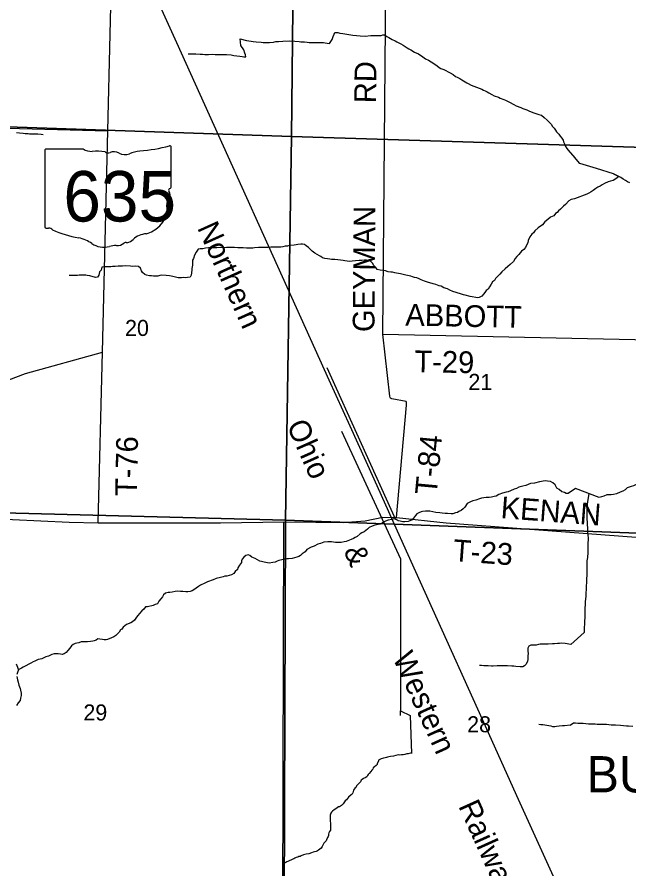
# Model space of a CAD drawing. Extents: x 1588073 to 2013523, y 1090242 to 1357120.
# Drawn here: x 1754621 to 1763053, y 1191885 to 1203633 of the extents above; entities that cross this region are included whole.
import ezdxf

# ---------------------------------------------------------------- set-up
doc = ezdxf.new("R2010")
doc.units = 0
for name, color, linetype in [('GM_X_Corporation_Text', 7, 'Continuous'), ('GM_X_Minor_River', 7, 'Continuous'), ('GM_X_Rail_Line', 7, 'Continuous'), ('GM_X_Rail_Line_Text', 7, 'Continuous'), ('GM_X_Section', 7, 'Continuous'), ('GM_X_Section_Text', 7, 'Continuous'), ('GM_X_State_Location', 7, 'Continuous'), ('GM_X_State_Route', 7, 'Continuous'), ('GM_X_State_Shield', 7, 'Continuous'), ('GM_X_Township_Road', 7, 'Continuous'), ('GM_X_Township_Road_Text', 7, 'Continuous')]:
    doc.layers.add(name, color=color, linetype=linetype)

msp = doc.modelspace()

# ---------------------------------------------------------------- linework, layer by layer
at = {"layer": 'GM_X_Minor_River'}
for p, q in [((1758889, 1198801), (1759836, 1196705)), ((1759092, 1197922), (1759904, 1196164)), ((1759904, 1196164), (1759904, 1196164)), ((1759904, 1196164), (1759905, 1194064)), ((1759905, 1194001), (1759905, 1194068)), ((1759905, 1194068), (1760040, 1194001)), ((1760040, 1194001), (1760040, 1194001)), ((1760040, 1194001), (1760055, 1193477))]:
    msp.add_line(p, q, dxfattribs=at)
for points in [[(1756979, 1203124), (1757025, 1203127), (1757085, 1203123), (1757145, 1203121), (1757177, 1203121), (1757207, 1203117), (1757233, 1203115), (1757261, 1203115), (1757321, 1203119), (1757351, 1203117), (1757399, 1203118), (1757479, 1203114), (1757505, 1203114), (1757573, 1203112), (1757606, 1203104), (1757690, 1203092), (1757722, 1203088), (1757748, 1203086), (1757774, 1203083), (1757768, 1203113), (1757758, 1203135), (1757746, 1203179), (1757707, 1203241), (1757701, 1203285), (1757695, 1203331), (1757781, 1203309), (1757847, 1203301), (1757873, 1203295), (1757916, 1203289), (1757984, 1203284), (1758014, 1203282), (1758102, 1203280), (1758154, 1203286), (1758188, 1203294), (1758222, 1203294), (1758282, 1203298), (1758374, 1203303), (1758450, 1203299), (1758508, 1203297), (1758532, 1203293), (1758583, 1203289), (1758617, 1203285), (1758647, 1203283), (1758679, 1203282), (1758719, 1203280), (1758759, 1203280), (1758783, 1203282), (1758805, 1203282), (1758843, 1203280), (1758869, 1203276), (1758895, 1203274), (1758925, 1203270), (1758947, 1203294), (1758963, 1203324), (1758979, 1203365), (1758989, 1203395), (1758999, 1203421), (1759043, 1203419), (1759071, 1203411), (1759111, 1203405), (1759193, 1203393), (1759247, 1203381), (1759347, 1203372), (1759420, 1203368), (1759494, 1203376), (1759522, 1203378), (1759584, 1203376), (1759638, 1203380), (1759660, 1203385), (1759684, 1203385), (1759716, 1203363), (1759746, 1203349), (1759792, 1203321), (1759830, 1203303), (1759854, 1203293), (1759911, 1203261), (1759943, 1203245), (1759971, 1203227), (1759997, 1203209), (1760021, 1203193), (1760047, 1203179), (1760099, 1203147), (1760153, 1203123), (1760213, 1203085), (1760250, 1203055), (1760292, 1203039), (1760364, 1202994), (1760412, 1202962), (1760440, 1202936), (1760462, 1202924), (1760502, 1202908), (1760589, 1202864), (1760631, 1202842), (1760661, 1202814), (1760685, 1202802), (1760723, 1202786), (1760749, 1202768), (1760773, 1202752), (1760817, 1202726), (1760839, 1202714), (1760880, 1202694)], [(1760880, 1202694), (1760952, 1202664), (1760990, 1202650), (1761026, 1202636), (1761050, 1202625), (1761072, 1202615), (1761098, 1202601), (1761124, 1202589), (1761162, 1202565), (1761198, 1202547), (1761254, 1202529), (1761279, 1202513), (1761329, 1202497), (1761351, 1202485), (1761405, 1202461), (1761467, 1202427), (1761501, 1202407), (1761565, 1202385), (1761591, 1202371), (1761644, 1202354), (1761674, 1202338), (1761730, 1202318), (1761756, 1202308), (1761812, 1202290), (1761846, 1202278), (1761886, 1202246), (1761924, 1202210), (1761948, 1202188), (1761981, 1202154), (1762001, 1202124), (1762021, 1202100), (1762043, 1202072), (1762057, 1202048), (1762089, 1202018), (1762107, 1201992), (1762129, 1201964), (1762145, 1201934), (1762153, 1201910), (1762164, 1201884), (1762176, 1201856), (1762198, 1201818), (1762214, 1201796), (1762308, 1201693)], [(1754614, 1202041), (1754654, 1202037), (1754706, 1202033), (1754732, 1202029), (1754772, 1202025), (1754794, 1202023), (1754856, 1202024), (1754880, 1202022), (1754906, 1202020), (1754951, 1202016), (1754979, 1202014)], [(1762841, 1201471), (1762606, 1201542), (1762376, 1201615), (1762302, 1201700)], [(1762915, 1201434), (1762873, 1201400), (1762834, 1201380), (1762800, 1201371), (1762768, 1201359), (1762716, 1201339), (1762683, 1201318), (1762655, 1201302), (1762623, 1201286), (1762595, 1201268), (1762558, 1201241), (1762532, 1201223), (1762500, 1201205), (1762472, 1201189), (1762303, 1201128)], [(1763066, 1201346), (1763035, 1201358), (1763007, 1201377), (1762975, 1201397), (1762941, 1201421), (1762913, 1201436), (1762875, 1201454), (1762841, 1201471), (1762915, 1201434)], [(1762303, 1201128), (1762256, 1201118), (1762224, 1201096), (1762178, 1201046), (1762150, 1201024), (1762112, 1200985), (1762084, 1200961), (1762062, 1200939), (1762040, 1200925), (1762018, 1200893), (1761974, 1200871), (1761936, 1200842), (1761896, 1200808), (1761860, 1200766), (1761800, 1200728), (1761754, 1200684), (1761738, 1200657), (1761714, 1200639), (1761688, 1200603), (1761666, 1200551), (1761658, 1200517), (1761641, 1200489), (1761627, 1200455), (1761605, 1200426), (1761571, 1200406), (1761537, 1200356), (1761509, 1200330), (1761483, 1200304), (1761461, 1200264), (1761415, 1200221), (1761385, 1200195), (1761347, 1200161), (1761301, 1200117), (1761275, 1200087), (1761249, 1200066), (1761213, 1200026), (1761199, 1200000), (1761175, 1199982), (1761153, 1199950), (1761131, 1199914), (1761111, 1199880), (1761087, 1199860), (1761065, 1199833), (1761050, 1199809), (1761026, 1199785), (1760990, 1199765), (1760964, 1199763), (1760941, 1199765), (1760893, 1199775), (1760867, 1199781), (1760797, 1199799), (1760771, 1199804), (1760731, 1199818), (1760627, 1199846), (1760585, 1199866), (1760555, 1199884), (1760504, 1199900), (1760464, 1199920), (1760440, 1199926), (1760390, 1199944), (1760356, 1199956), (1760278, 1199978), (1760236, 1199991), (1760214, 1199999), (1760188, 1200011), (1760162, 1200021), (1760128, 1200035), (1760099, 1200041), (1760069, 1200051), (1760047, 1200061), (1760001, 1200069), (1759979, 1200073), (1759907, 1200091), (1759877, 1200097), (1759851, 1200101), (1759829, 1200105), (1759795, 1200113), (1759773, 1200116), (1759737, 1200120), (1759699, 1200134), (1759671, 1200138), (1759625, 1200142), (1759584, 1200150), (1759564, 1200180), (1759536, 1200206), (1759518, 1200238), (1759498, 1200260), (1759472, 1200274), (1759438, 1200280), (1759408, 1200278), (1759374, 1200276), (1759334, 1200276), (1759286, 1200270), (1759240, 1200265), (1759206, 1200263), (1759168, 1200267), (1759139, 1200273), (1759115, 1200277), (1759043, 1200283), (1758999, 1200289), (1758975, 1200291)], [(1758975, 1200291), (1758953, 1200291), (1758929, 1200293), (1758897, 1200297), (1758861, 1200304), (1758831, 1200314), (1758809, 1200330), (1758787, 1200340), (1758723, 1200378), (1758688, 1200406), (1758638, 1200456), (1758606, 1200480), (1758582, 1200496), (1758556, 1200502), (1758530, 1200502), (1758490, 1200496), (1758466, 1200490), (1758440, 1200488), (1758372, 1200482), (1758346, 1200475), (1758316, 1200471), (1758284, 1200465), (1758254, 1200461), (1758214, 1200459), (1758155, 1200461), (1758119, 1200461), (1758083, 1200457), (1758053, 1200455), (1757947, 1200454), (1757893, 1200448), (1757871, 1200446), (1757839, 1200444), (1757785, 1200446), (1757737, 1200448), (1757691, 1200452), (1757665, 1200451), (1757619, 1200455), (1757559, 1200453), (1757505, 1200453), (1757466, 1200451), (1757418, 1200453), (1757372, 1200451), (1757296, 1200448), (1757258, 1200448), (1757220, 1200444), (1757182, 1200438), (1757142, 1200436), (1757116, 1200430), (1757090, 1200390), (1757068, 1200348), (1757054, 1200305), (1757040, 1200281), (1757038, 1200247), (1757037, 1200211), (1757031, 1200167), (1757029, 1200145), (1757025, 1200105), (1757019, 1200075), (1757005, 1200047), (1756969, 1200040), (1756941, 1200038), (1756915, 1200040), (1756887, 1200038), (1756843, 1200038), (1756803, 1200046), (1756769, 1200056), (1756722, 1200062), (1756674, 1200068), (1756612, 1200074), (1756588, 1200067), (1756560, 1200061), (1756534, 1200059), (1756500, 1200059), (1756472, 1200063), (1756444, 1200065), (1756406, 1200075), (1756380, 1200081), (1756350, 1200109), (1756338, 1200133), (1756324, 1200171), (1756295, 1200193), (1756259, 1200197), (1756217, 1200195), (1756185, 1200197), (1756113, 1200200), (1756073, 1200198), (1756047, 1200198), (1756013, 1200196), (1755971, 1200194), (1755935, 1200192), (1755911, 1200190), (1755879, 1200188), (1755853, 1200188), (1755815, 1200186), (1755789, 1200185), (1755779, 1200141), (1755759, 1200119), (1755747, 1200071), (1755729, 1200047), (1755703, 1200039), (1755625, 1200065)], [(1755625, 1200065), (1755589, 1200069), (1755567, 1200071), (1755541, 1200075), (1755515, 1200072), (1755477, 1200072), (1755453, 1200070), (1755412, 1200068), (1755362, 1200068), (1755340, 1200070)], [(1762315, 1197133), (1762217, 1197061), (1762187, 1197063), (1762165, 1197075), (1762130, 1197087), (1762090, 1197117), (1762060, 1197135), (1762038, 1197181), (1762004, 1197211), (1761970, 1197229), (1761932, 1197233), (1761898, 1197235), (1761820, 1197223), (1761752, 1197206), (1761698, 1197202), (1761630, 1197172), (1761589, 1197162), (1761535, 1197148), (1761505, 1197131), (1761471, 1197123), (1761421, 1197099), (1761389, 1197087), (1761361, 1197081), (1761309, 1197065), (1761261, 1197047), (1761225, 1197028), (1761195, 1197022), (1761159, 1197012), (1761129, 1197008), (1761085, 1197008), (1761021, 1196998), (1760995, 1196988), (1760945, 1196969), (1760903, 1196961), (1760871, 1196949), (1760825, 1196927), (1760791, 1196875), (1760767, 1196849), (1760743, 1196829), (1760711, 1196814), (1760689, 1196800), (1760663, 1196796), (1760627, 1196784), (1760603, 1196782), (1760553, 1196786), (1760519, 1196788), (1760479, 1196792), (1760447, 1196794), (1760391, 1196801), (1760311, 1196817), (1760281, 1196819), (1760250, 1196817), (1760210, 1196815), (1760188, 1196811), (1760158, 1196795), (1760130, 1196781), (1760110, 1196759), (1760084, 1196724), (1760064, 1196700), (1760032, 1196686), (1760010, 1196676), (1759964, 1196670), (1759938, 1196670), (1759902, 1196680), (1759874, 1196688), (1759846, 1196706), (1759812, 1196712), (1759784, 1196706), (1759736, 1196695), (1759700, 1196679), (1759678, 1196671), (1759656, 1196657), (1759626, 1196641), (1759598, 1196637), (1759550, 1196627), (1759516, 1196613), (1759474, 1196592), (1759452, 1196572), (1759428, 1196552), (1759406, 1196534), (1759374, 1196520), (1759350, 1196506), (1759306, 1196468), (1759280, 1196455), (1759258, 1196443), (1759226, 1196429), (1759204, 1196421), (1759156, 1196401), (1759128, 1196395), (1759086, 1196387), (1759062, 1196385), (1759010, 1196387), (1758980, 1196392), (1758956, 1196394), (1758926, 1196396), (1758904, 1196396), (1758848, 1196390), (1758802, 1196374), (1758768, 1196364), (1758714, 1196336), (1758673, 1196323)], [(1763471, 1197221), (1763433, 1197221), (1763399, 1197223), (1763296, 1197224), (1763256, 1197223), (1763208, 1197207), (1763172, 1197187), (1763142, 1197180), (1763115, 1197168), (1763083, 1197160), (1763057, 1197150), (1763029, 1197139), (1763003, 1197113), (1762968, 1197097), (1762930, 1197080), (1762880, 1197058), (1762842, 1197048), (1762809, 1197045), (1762777, 1197045), (1762749, 1197043), (1762707, 1197028), (1762677, 1197018), (1762643, 1197008), (1762315, 1197133)], [(1762502, 1197062), (1762482, 1196946), (1762477, 1196914), (1762475, 1196864), (1762473, 1196835), (1762472, 1196759), (1762473, 1196713), (1762477, 1196665), (1762479, 1196631), (1762480, 1196589), (1762482, 1196553), (1762484, 1196527), (1762487, 1196489), (1762489, 1196452), (1762491, 1196422), (1762488, 1196384), (1762487, 1196286), (1762485, 1196248), (1762480, 1196182), (1762472, 1196136), (1762471, 1196018), (1762472, 1195975), (1762472, 1195931), (1762469, 1195889), (1762467, 1195833), (1762464, 1195793), (1762464, 1195745), (1762459, 1195687), (1762457, 1195641), (1762454, 1195609), (1762450, 1195567), (1762450, 1195525), (1762447, 1195491), (1762445, 1195442), (1762444, 1195348), (1762441, 1195306), (1762439, 1195258), (1762437, 1195220), (1762436, 1195182), (1762438, 1195148), (1762252, 1194981)], [(1758673, 1196323), (1758615, 1196289), (1758590, 1196259), (1758548, 1196231), (1758528, 1196209), (1758502, 1196195), (1758476, 1196184), (1758444, 1196174), (1758414, 1196166), (1758361, 1196162), (1758339, 1196162), (1758305, 1196158), (1758271, 1196150), (1758229, 1196138), (1758207, 1196130), (1758179, 1196117), (1758145, 1196111), (1758097, 1196103), (1758047, 1196109), (1758025, 1196115), (1757991, 1196127), (1757967, 1196131), (1757933, 1196147), (1757903, 1196165), (1757855, 1196185), (1757831, 1196209), (1757808, 1196219), (1757772, 1196207), (1757748, 1196186), (1757723, 1196158), (1757715, 1196134), (1757713, 1196110), (1757685, 1196074), (1757665, 1196036), (1757661, 1196014), (1757627, 1195986), (1757609, 1195961), (1757575, 1195943), (1757545, 1195933), (1757511, 1195925), (1757483, 1195921), (1757461, 1195913), (1757425, 1195903), (1757365, 1195889), (1757323, 1195872), (1757245, 1195844), (1757207, 1195828), (1757151, 1195798), (1757121, 1195780), (1757087, 1195755), (1757055, 1195733), (1757033, 1195721), (1757005, 1195713), (1756975, 1195705), (1756945, 1195707), (1756907, 1195709), (1756872, 1195711), (1756826, 1195715), (1756802, 1195709), (1756758, 1195700), (1756728, 1195698), (1756702, 1195698), (1756666, 1195690), (1756638, 1195666), (1756626, 1195640), (1756602, 1195610), (1756576, 1195576), (1756556, 1195543), (1756524, 1195531), (1756496, 1195519), (1756418, 1195501), (1756390, 1195499), (1756366, 1195467), (1756342, 1195445), (1756308, 1195410), (1756283, 1195382), (1756269, 1195358), (1756239, 1195318), (1756213, 1195294), (1756191, 1195280), (1756127, 1195257), (1756085, 1195219), (1756067, 1195193), (1756045, 1195181), (1756029, 1195149), (1756007, 1195127), (1755981, 1195105), (1755955, 1195088), (1755923, 1195072), (1755869, 1195050), (1755847, 1195046), (1755823, 1195046), (1755799, 1195048), (1755763, 1195056), (1755735, 1195058), (1755709, 1195042), (1755685, 1195032), (1755663, 1195026), (1755635, 1195023), (1755590, 1195019), (1755534, 1195019)], [(1755534, 1195019), (1755504, 1195015), (1755472, 1195005), (1755446, 1195001), (1755420, 1194995), (1755396, 1194981), (1755370, 1194963), (1755350, 1194928), (1755322, 1194900), (1755298, 1194870), (1755270, 1194852), (1755242, 1194842), (1755220, 1194848), (1755188, 1194850), (1755130, 1194852), (1755102, 1194843), (1755074, 1194829), (1755052, 1194821), (1755018, 1194809), (1754988, 1194795), (1754962, 1194785), (1754940, 1194779), (1754912, 1194773), (1754866, 1194751), (1754844, 1194742), (1754812, 1194722), (1754784, 1194708), (1754744, 1194686), (1754706, 1194666), (1754684, 1194652), (1754656, 1194642), (1754632, 1194634)], [(1762252, 1194981), (1762176, 1194994), (1762122, 1194998), (1762098, 1194995), (1762070, 1194995), (1762028, 1194989), (1761998, 1194989), (1761942, 1194983), (1761828, 1194983), (1761806, 1194979), (1761776, 1194972), (1761722, 1194972), (1761700, 1194972), (1761672, 1194956), (1761660, 1194930), (1761662, 1194890), (1761664, 1194858), (1761662, 1194824), (1761660, 1194802), (1761658, 1194776), (1761654, 1194746), (1761634, 1194705), (1761612, 1194685), (1761590, 1194673), (1761554, 1194671), (1761494, 1194677), (1761468, 1194681), (1761440, 1194681), (1761378, 1194687), (1761348, 1194687), (1761312, 1194688), (1761282, 1194688), (1761236, 1194684), (1761182, 1194682), (1761158, 1194682), (1761114, 1194684), (1761079, 1194688), (1761055, 1194688), (1761021, 1194690), (1760995, 1194692)], [(1754641, 1194637), (1754630, 1194662), (1754624, 1194688), (1754614, 1194710)], [(1754641, 1194633), (1754625, 1194593), (1754620, 1194567)], [(1754618, 1194541), (1754626, 1194491), (1754638, 1194459), (1754644, 1194421), (1754664, 1194375), (1754670, 1194351), (1754678, 1194311), (1754676, 1194276), (1754667, 1194242), (1754663, 1194206), (1754637, 1194178), (1754615, 1194140)], [(1762243, 1193867), (1762289, 1193902), (1762317, 1193900), (1762349, 1193896), (1762381, 1193896), (1762424, 1193897), (1762494, 1193888), (1762522, 1193886), (1762586, 1193885), (1762614, 1193883), (1762676, 1193881), (1762746, 1193880), (1762810, 1193875), (1762868, 1193873), (1762936, 1193868), (1763019, 1193859), (1763045, 1193857), (1763105, 1193854)], [(1762243, 1193867), (1762167, 1193861), (1762137, 1193859), (1762091, 1193854), (1762057, 1193848), (1762033, 1193844), (1762003, 1193846), (1761981, 1193854), (1761947, 1193860), (1761893, 1193868), (1761867, 1193872), (1761839, 1193874), (1761813, 1193878)], [(1760056, 1193480), (1760042, 1193484), (1760010, 1193475), (1759994, 1193471), (1759978, 1193466), (1759964, 1193464), (1759943, 1193461), (1759921, 1193457), (1759889, 1193454), (1759871, 1193457), (1759841, 1193449), (1759809, 1193442), (1759767, 1193435), (1759742, 1193432), (1759728, 1193426), (1759714, 1193422), (1759696, 1193417), (1759672, 1193413), (1759640, 1193402), (1759619, 1193395), (1759603, 1193387), (1759601, 1193371), (1759584, 1193340), (1759582, 1193326), (1759571, 1193310), (1759545, 1193294), (1759530, 1193279), (1759522, 1193261), (1759512, 1193247), (1759497, 1193229), (1759474, 1193202), (1759458, 1193188), (1759448, 1193173), (1759439, 1193155), (1759419, 1193141), (1759395, 1193132), (1759376, 1193120), (1759362, 1193109), (1759352, 1193089), (1759339, 1193075), (1759321, 1193054), (1759300, 1193030), (1759296, 1193012), (1759279, 1193006), (1759267, 1192985), (1759259, 1192971), (1759246, 1192937), (1759239, 1192917), (1759225, 1192908), (1759188, 1192876), (1759159, 1192839), (1759141, 1192823), (1759132, 1192810), (1759126, 1192796), (1759114, 1192782), (1759091, 1192761), (1759063, 1192743), (1759049, 1192740), (1759030, 1192730), (1759012, 1192714), (1758990, 1192699), (1758967, 1192682), (1758955, 1192668), (1758944, 1192654), (1758936, 1192626), (1758937, 1192606), (1758936, 1192576), (1758938, 1192556), (1758939, 1192502), (1758940, 1192466), (1758939, 1192420), (1758928, 1192404), (1758918, 1192384), (1758915, 1192366), (1758911, 1192348), (1758906, 1192332), (1758898, 1192318), (1758885, 1192289), (1758879, 1192273), (1758862, 1192253), (1758850, 1192239), (1758840, 1192222), (1758825, 1192194), (1758810, 1192170), (1758792, 1192157), (1758774, 1192145), (1758759, 1192137), (1758743, 1192126), (1758721, 1192120), (1758701, 1192115), (1758677, 1192109), (1758644, 1192096), (1758604, 1192089), (1758568, 1192080), (1758537, 1192067), (1758523, 1192059), (1758505, 1192056), (1758491, 1192046), (1758465, 1192043), (1758449, 1192033), (1758434, 1192025)], [(1758434, 1192025), (1758420, 1192020), (1758402, 1192012), (1758372, 1191999), (1758353, 1191989), (1758339, 1191982), (1758323, 1191974), (1758307, 1191965)]]:
    msp.add_lwpolyline(points, dxfattribs=at)
at = {"layer": 'GM_X_Rail_Line'}
msp.add_lwpolyline([(1762274, 1191202), (1762241, 1191275), (1761533, 1192842), (1760970, 1194091), (1760415, 1195321), (1759947, 1196359), (1759540, 1197259), (1759211, 1197990), (1758923, 1198626), (1756824, 1203275), (1756439, 1204131), (1756183, 1204700), (1756056, 1204979), (1755969, 1205174), (1755700, 1205772), (1755471, 1206278), (1755179, 1206926), (1755002, 1207318), (1754804, 1207757), (1754643, 1208116), (1753615, 1210421)], dxfattribs=at)
at = {"layer": 'GM_X_Section'}
for points in [[(1753547, 1207474), (1758457, 1207275), (1758404, 1201985), (1753407, 1202156)], [(1758457, 1207275), (1763664, 1207109), (1763564, 1201823), (1758404, 1201985)], [(1753407, 1202156), (1758404, 1201985), (1758320, 1196693), (1753183, 1196826)], [(1763564, 1201823), (1763676, 1196498), (1758320, 1196693), (1758404, 1201985)], [(1753183, 1196826), (1758320, 1196693), (1758303, 1191389), (1753017, 1191547)], [(1758320, 1196693), (1763676, 1196498), (1763648, 1191188), (1758303, 1191389)]]:
    msp.add_lwpolyline(points, close=True, dxfattribs=at)
at = {"layer": 'GM_X_State_Route'}
msp.add_lwpolyline([(1752841, 1186194), (1753004, 1191531), (1753114, 1194718), (1753174, 1196805), (1753232, 1198124), (1753415, 1198218), (1754735, 1198719), (1755798, 1199012), (1755870, 1202063), (1755938, 1204735), (1756023, 1208199)], dxfattribs=at)
at = {"layer": 'GM_X_State_Shield'}
for p, q in [((1755004, 1201795), (1755004, 1200738)), ((1755531, 1201813), (1755021, 1201813)), ((1756744, 1201287), (1756744, 1201839)), ((1756744, 1201287), (1756744, 1201287))]:
    msp.add_line(p, q, dxfattribs=at)
for centre, major_axis, start_param, end_param in [((1755024, 1201797), (20.2, 0), 1.712693, 3.28349), ((1755652, 1201936), (196, 0), 4.042523, 4.731795), ((1755717, 1201220), (702, 0), 1.404758, 1.657858), ((1755877, 1201803), (56.4, 0), 3.836095, 5.185415), ((1755959, 1201681), (117, 0), 0.950623, 2.079405), ((1756111, 1201848), (141, 0), 4.081561, 5.145723), ((1756360, 1201491), (371, 0), 1.699011, 2.107814), ((1756125, 1203254), (1845, 0), 4.814394, 5.042369), ((1756725, 1201842), (19.4, 0), 6.141152, 7.989035), ((1756724, 1201285), (20.7, 0), 5.05454, 6.418171), ((1756740, 1201246), (30, 0), 1.883978, 3.671073), ((1756549, 1201176), (180, 0), 5.934695, 6.695948), ((1756814, 1201055), (131, 0), 2.387724, 3.262537), ((1756228, 1200985), (462, 0), 5.101752, 6.440018), ((1755024, 1200736), (20.3, 0), 3.00124, 4.508301), ((1755027, 1200844), (155, 0), 4.665946, 4.897461), ((1755059, 1200677), (56, 0), 0.519207, 1.627899), ((1755766, 1201627), (1333, 0), 4.195997, 4.488961), ((1755368, 1200264), (417, 0), 0.823519, 1.323587), ((1756423, 1200442), (253, 0), 1.647645, 2.488434), ((1755819, 1200672), (265, 0), 4.026481, 4.996735), ((1755972, 1200307), (217, 0), 1.495662, 1.94098), ((1755992, 1200593), (141, 0), 4.691044, 5.507374), ((1756119, 1200491), (39.7, 0), 1.147584, 2.315152), ((1756102, 1200636), (149, 0), 4.937069, 5.64225)]:
    msp.add_ellipse(centre, major_axis=major_axis, ratio=0.8, start_param=start_param, end_param=end_param, dxfattribs=at)
at = {"layer": 'GM_X_Township_Road'}
for points in [[(1759662, 1199261), (1759706, 1204567)], [(1752047, 1202165), (1755870, 1202063)], [(1759662, 1199261), (1766176, 1199123)], [(1759852, 1196730), (1759990, 1198281), (1759990, 1198316), (1759981, 1198332), (1759787, 1198368), (1759769, 1198377), (1759763, 1198385), (1759759, 1198403), (1759662, 1199261)], [(1755739, 1196659), (1755798, 1199012)], [(1753174, 1196805), (1754557, 1196706), (1755338, 1196668), (1755739, 1196659), (1757426, 1196658), (1758295, 1196671)], [(1758295, 1196671), (1758736, 1196666), (1759115, 1196665), (1759416, 1196685), (1759663, 1196736), (1759852, 1196730), (1760535, 1196659), (1763395, 1196443), (1766234, 1196459)], [(1758285, 1191354), (1758295, 1196671)]]:
    msp.add_lwpolyline(points, dxfattribs=at)

# ---------------------------------------------------------------- texts
at = {"layer": 'GM_X_Corporation_Text'}
msp.add_text('BURGOON', height=500, rotation=0, dxfattribs=at).set_placement((1762469, 1192941))
at = {"layer": 'GM_X_Rail_Line_Text'}
for s, rotation, p in [('Northern', 294.2665, (1757099, 1200727)), ('Ohio', 294.0391, (1758331, 1198004)), ('&', 294.5159, (1759116, 1196272)), ('Western', 294.3547, (1759792, 1194799)), ('Railway', 294.2773, (1760698, 1192754))]:
    msp.add_text(s, height=299, rotation=rotation, dxfattribs=at).set_placement(p)
at = {"layer": 'GM_X_Section_Text'}
for s, p in [('20', (1756109, 1199235)), ('21', (1760841, 1198491)), ('29', (1755535, 1193933)), ('28', (1760824, 1193770))]:
    msp.add_text(s, height=221, rotation=0, dxfattribs=at).set_placement(p)
at = {"layer": 'GM_X_State_Location'}
for s in ['s', 'r']:
    msp.add_text(s, height=1, dxfattribs=at).set_placement((1755855, 1201196))
msp.add_text('635', height=1, rotation=0, dxfattribs=at).set_placement((1755502, 1201124))
at = {"layer": 'GM_X_State_Shield'}
msp.add_text('635', height=696.1, dxfattribs=at).set_placement((1755259, 1200813))
at = {"layer": 'GM_X_Township_Road_Text'}
for s, rotation, p in [('RD', 89.5045, (1759568, 1202443)), ('GEYMAN', 89.5306, (1759546, 1199288)), ('ABBOTT', 358.7958, (1759970, 1199379)), ('T-29', 358.9397, (1760094, 1198736)), ('T-76', 88.9397, (1756273, 1197025)), ('T-84', 84.6775, (1760403, 1197035)), ('KENAN', 355.6767, (1761279, 1196724)), ('T-23', 355.764, (1760620, 1196133))]:
    msp.add_text(s, height=300, rotation=rotation, dxfattribs=at).set_placement(p)

doc.saveas('drawing.dxf')
